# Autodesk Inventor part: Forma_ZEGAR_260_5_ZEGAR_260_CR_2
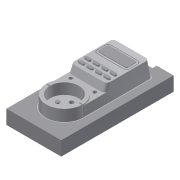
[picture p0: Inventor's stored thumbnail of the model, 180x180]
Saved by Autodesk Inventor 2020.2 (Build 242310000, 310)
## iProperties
Created: 2015-01
Part Number: Forma_ZEGAR_260_5_ZEGAR_260_CR_2
Material: Ogólny
Document SubType Name: Modeling
Designer: F.Stasiak
Density: 1 g/cm^3
Appearance: Domyślna
Catalog Web Link: www.expertbooks.pl
Manager: www.cadconsulting.pl
Company: Fabian Stasiak CAD Consulting
Author: F.Stasiak
Subject: Zbiór ćwiczeń. Autodesk Inventor 2020. Kurs Professional
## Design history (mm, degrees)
node "Forma_ZEGAR_260_4_ZEGAR_260_CR_Base"
feature "Bryła1::Forma_ZEGAR_260_4_ZEGAR_260_CR_Base"
tag "Bryła wyprowadzona1"
node "Bryła1"
feature "Forma_ZEGAR_260_4_ZEGAR_260_CR_Base_Bodies"
